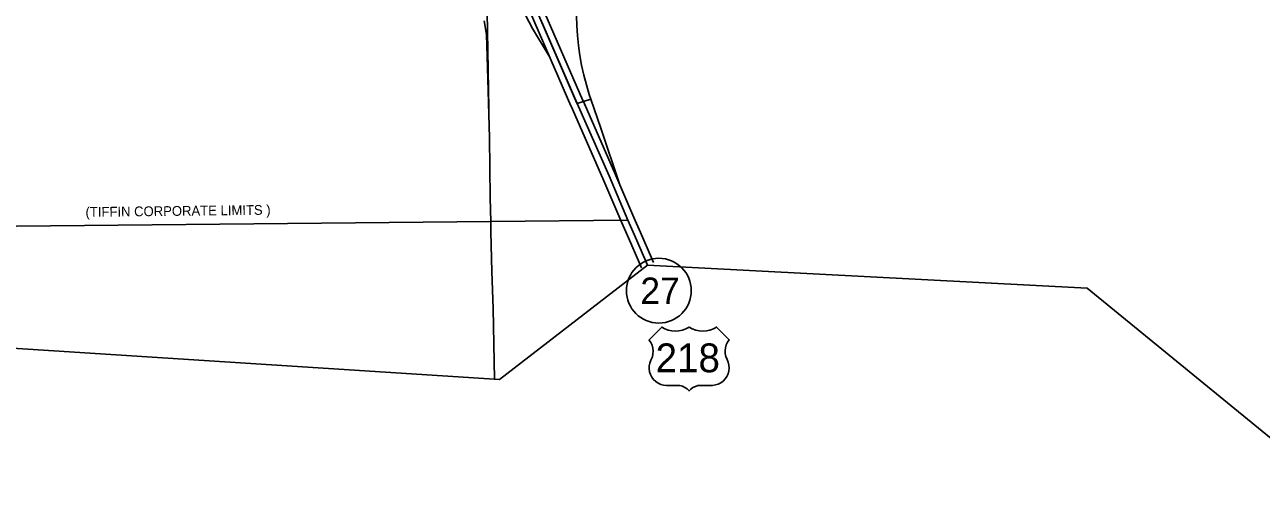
# Model space of a CAD drawing. Extents: x 281.94 to 289.14, y 116.09 to 120.89.
# Drawn here: x 285.132 to 286.65, y 117.106 to 117.681 of the extents above; entities that cross this region are included whole.
import ezdxf

# ---------------------------------------------------------------- set-up
doc = ezdxf.new("R2010")
doc.units = 0
for name, color, linetype in [('tdCiCityStreetCL', 7, 'Continuous'), ('tdCiCorpBndry', 7, 'Continuous'), ('tdCiCorpBndryPart', 7, 'Continuous'), ('tdCiCorpBndryTxt', 7, 'Continuous'), ('tdCiIntRamp', 7, 'Continuous'), ('tdCiIntRampCL', 7, 'Continuous'), ('tdCiMapPltShpe', 7, 'Continuous'), ('tdCiPriCL', 7, 'Continuous'), ('tdCiPriDiv', 7, 'Continuous'), ('tdCiPriDivCL', 7, 'Continuous'), ('tdCiSecCL', 7, 'Continuous'), ('tdCiSectLine', 7, 'Continuous'), ('tdCiShieldPriStRte', 7, 'Continuous'), ('tdCiShieldPriUsRte', 7, 'Continuous')]:
    doc.layers.add(name, color=color, linetype=linetype)

msp = doc.modelspace()

# ---------------------------------------------------------------- linework, layer by layer
at = {"layer": 'tdCiCityStreetCL'}
msp.add_lwpolyline([(285.7041, 117.4389), (285.7035, 117.4678), (285.7028, 117.5415), (285.7003, 117.6281), (285.6988, 117.6685), (285.6961, 117.6853)], dxfattribs=at)
at = {"layer": 'tdCiCorpBndry'}
msp.add_lwpolyline([(284.955, 117.4315), (285.7041, 117.4389), (285.8725, 117.4406), (285.8494, 117.4949), (285.8102, 117.5838), (285.7652, 117.6875)], dxfattribs=at)
at = {"layer": 'tdCiCorpBndryPart'}
msp.add_lwpolyline([(284.955, 117.4315), (285.7041, 117.4389), (285.8725, 117.4406), (285.8494, 117.4949), (285.8102, 117.5838), (285.7652, 117.6875)], dxfattribs=at)
at = {"layer": 'tdCiIntRamp'}
for points in [[(285.7474, 117.6915), (285.7556, 117.6761), (285.7772, 117.6397)], [(285.8627, 117.484), (285.8395, 117.5536), (285.8271, 117.5892), (285.8251, 117.595), (285.8216, 117.6068), (285.8184, 117.6187), (285.8158, 117.6307), (285.8136, 117.6427), (285.8119, 117.6549), (285.8106, 117.6671), (285.8098, 117.6794), (285.8095, 117.6916)]]:
    msp.add_lwpolyline(points, dxfattribs=at)
at = {"layer": 'tdCiIntRampCL'}
msp.add_lwpolyline([(285.8102, 117.5838), (285.8271, 117.5892), (285.8251, 117.595), (285.8216, 117.6068), (285.8184, 117.6187), (285.8158, 117.6307), (285.8136, 117.6427), (285.8119, 117.6549), (285.8106, 117.6671), (285.8098, 117.6794), (285.8095, 117.6916)], dxfattribs=at)
at = {"layer": 'tdCiMapPltShpe'}
for p, q in [((283.629, 117.3793), (285.715, 117.2447)), ((285.715, 117.2447), (285.8966, 117.3851))]:
    msp.add_line(p, q, dxfattribs=at)
msp.add_lwpolyline([(285.8966, 117.3851), (286.4365, 117.3571), (286.7431, 117.1063)], dxfattribs=at)
at = {"layer": 'tdCiPriCL'}
msp.add_lwpolyline([(285.8966, 117.3851), (285.894, 117.3909), (285.8805, 117.4222), (285.8725, 117.4406), (285.8494, 117.4949), (285.8102, 117.5838), (285.81, 117.5841), (285.7552, 117.7107), (285.7546, 117.7119), (285.726, 117.7777), (285.7198, 117.7911), (285.7175, 117.796), (285.7096, 117.8128), (285.7054, 117.8217), (285.7013, 117.8307), (285.7011, 117.8312), (285.6861, 117.8636), (285.6812, 117.8741), (285.6717, 117.8968), (285.6717, 117.8968), (285.664, 117.9149), (285.6627, 117.9181), (285.6519, 117.9437), (285.6517, 117.9442)], dxfattribs=at)
at = {"layer": 'tdCiPriDiv'}
for points in [[(285.8893, 117.3818), (285.8867, 117.3877), (285.8732, 117.419), (285.8652, 117.4374), (285.842, 117.4917), (285.8029, 117.5806), (285.8027, 117.581), (285.7478, 117.7075), (285.7473, 117.7087), (285.7187, 117.7745), (285.7125, 117.7877), (285.7102, 117.7926), (285.7023, 117.8094), (285.6982, 117.8183), (285.694, 117.8275), (285.6938, 117.8279), (285.6789, 117.8602), (285.6739, 117.8708), (285.6643, 117.8937), (285.6643, 117.8937), (285.6567, 117.9118), (285.6554, 117.915), (285.6445, 117.9406), (285.6431, 117.9439)], [(285.9039, 117.3884), (285.9014, 117.3941), (285.8879, 117.4254), (285.8799, 117.4437), (285.8567, 117.4981), (285.8175, 117.587), (285.8174, 117.5873), (285.7625, 117.7139), (285.762, 117.7151), (285.7333, 117.781), (285.727, 117.7945), (285.7247, 117.7994), (285.7168, 117.8162), (285.7127, 117.825), (285.7086, 117.834), (285.7084, 117.8345), (285.6934, 117.8669), (285.6886, 117.8773), (285.6791, 117.8999), (285.6791, 117.8999), (285.6714, 117.918), (285.6701, 117.9212), (285.6644, 117.9346), (285.6603, 117.9445)]]:
    msp.add_lwpolyline(points, dxfattribs=at)
at = {"layer": 'tdCiPriDivCL'}
msp.add_lwpolyline([(285.8966, 117.3851), (285.894, 117.3909), (285.8805, 117.4222), (285.8725, 117.4406), (285.8494, 117.4949), (285.8102, 117.5838), (285.81, 117.5841), (285.7552, 117.7107), (285.7546, 117.7119), (285.726, 117.7777), (285.7198, 117.7911), (285.7175, 117.796), (285.7096, 117.8128), (285.7054, 117.8217), (285.7013, 117.8307), (285.7011, 117.8312), (285.6861, 117.8636), (285.6812, 117.8741), (285.6717, 117.8968), (285.6717, 117.8968), (285.664, 117.9149), (285.6627, 117.9181), (285.6519, 117.9437), (285.6517, 117.9442)], dxfattribs=at)
at = {"layer": 'tdCiSecCL'}
msp.add_lwpolyline([(285.7089, 117.2451), (285.7072, 117.3322), (285.7055, 117.3773), (285.7044, 117.4263), (285.7041, 117.4389)], dxfattribs=at)
at = {"layer": 'tdCiSectLine'}
msp.add_lwpolyline([(285.6708, 119.3069), (285.6871, 118.4319), (285.7018, 117.5775)], dxfattribs=at)
at = {"layer": 'tdCiShieldPriStRte'}
msp.add_circle((285.9106, 117.3539), 0.0398, dxfattribs=at)
at = {"layer": 'tdCiShieldPriUsRte'}
msp.add_lwpolyline([(285.9063, 117.3013), (285.9141, 117.3091), (285.918, 117.307), (285.9221, 117.3055), (285.9264, 117.3046), (285.9311, 117.3042), (285.9352, 117.3046), (285.9396, 117.3055), (285.9438, 117.307), (285.9478, 117.3091), (285.9517, 117.307), (285.9558, 117.3055), (285.9602, 117.3046), (285.9646, 117.3043), (285.969, 117.3046), (285.9733, 117.3055), (285.9775, 117.3069), (285.9815, 117.3091), (285.997, 117.2935), (285.9949, 117.2906), (285.9933, 117.2874), (285.9923, 117.2839), (285.9919, 117.2803), (285.9921, 117.2767), (285.9928, 117.2731), (285.9944, 117.2694), (285.9959, 117.266), (285.9967, 117.2625), (285.997, 117.2589), (285.9967, 117.2553), (285.9957, 117.2518), (285.9942, 117.2485), (285.9922, 117.2455), (285.9896, 117.2429), (285.9867, 117.2408), (285.9835, 117.2391), (285.9801, 117.2381), (285.9765, 117.2376), (285.9619, 117.2376), (285.9586, 117.2373), (285.9554, 117.2364), (285.9524, 117.2349), (285.9498, 117.2329), (285.9478, 117.2308), (285.9455, 117.2332), (285.9427, 117.2351), (285.9397, 117.2365), (285.9365, 117.2373), (285.9337, 117.2375), (285.9201, 117.2376), (285.9165, 117.2379), (285.913, 117.2388), (285.9097, 117.2402), (285.9067, 117.2423), (285.9041, 117.2447), (285.9019, 117.2476), (285.9002, 117.2508), (285.8991, 117.2543), (285.8986, 117.2579), (285.8987, 117.2615), (285.8994, 117.265), (285.9006, 117.2684), (285.9026, 117.2727), (285.9034, 117.2762), (285.9037, 117.2798), (285.9033, 117.2834), (285.9024, 117.2869), (285.9009, 117.2902), (285.8988, 117.2932), (285.8985, 117.2935)], close=True, dxfattribs=at)

# ---------------------------------------------------------------- texts
at = {"layer": 'tdCiCorpBndryTxt'}
msp.add_text('(TIFFIN CORPORATE LIMITS )', height=0.012, rotation=0.6912, dxfattribs=at).set_placement((285.2066, 117.4445))
at = {"layer": 'tdCiShieldPriStRte'}
msp.add_text('27', height=0.03246, dxfattribs=at).set_placement((285.8879, 117.3376))
at = {"layer": 'tdCiShieldPriUsRte'}
msp.add_text('218', height=0.03541, dxfattribs=at).set_placement((285.9066, 117.2537))

doc.saveas('drawing.dxf')
